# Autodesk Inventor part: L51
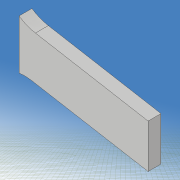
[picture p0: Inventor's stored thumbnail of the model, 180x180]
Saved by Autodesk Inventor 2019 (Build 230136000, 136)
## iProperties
Created: 2021-05
Part Number: L51
Material: 一般
Document SubType Name: Modeling
Designer: kikut
Density: 1 g/cm^3
Appearance: 既定
Mass: 0.00934248 g
Surface Area: 0.426451 cm^2
Volume: 0.00934248 cm^3
Author: kikut
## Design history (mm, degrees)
sketch "スケッチ1"
  geometry: L1 (80, 60)-(-80, 60); L2 (-80, 60)-(-80, -60); L3 (-80, -60)-(80, -60); L4 (80, -60)-(80, 60); L5 (80, 60)-(-80, -60); L6 (-80, 60)-(80, -60); 1 further point
  constraints: 12 end point, 2 midpoint, 2 parallel, 1 horizontal, 1 perpendicular
  dimensions: "d0" = 160 distance of L2.end L3.end; "d1" = 120 distance of L1.end L2.end
extrude "押し出し1" new body sketch "スケッチ1" stored distance "d2" = 0.6; taper "d3" = 0 deg
sketch "スケッチ2"
  geometry: L1 (-140, 0)-(140, 0) reference; L2 (0, -54)-(20, -30); L3 (0, 54)-(20, 30); L4 (0, -3)-(6.514, -3); L5 (6.514, -3)-(16, -6); L6 (16, -6)-(24, -3); L7 (24, -3)-(33.716, -3); L8 (0, 3)-(6.514, 3); L9 (6.514, 3)-(16, 6); L10 (16, 6)-(24, 3); L11 (24, 3)-(33.716, 3); L12 (0, -98)-(0, 98) reference; L13 (-100, -70)-(100, -70); L14 (100, -70)-(100, 70); L15 (100, 70)-(-100, 70); L16 (-100, 70)-(-100, -70); L17 (-100, -70)-(100, 70); L18 (100, -70)-(-100, 70); A1 r 60 centre (54.312, 28.5) between (0, 54) and (0, 3); A2 r 60 centre (54.312, -28.5) between (0, -3) and (0, -54); A3 r 18.111 centre (18, -12) between (20, -30) and (33.716, -3); A4 r 18.111 centre (18, 12) between (33.716, 3) and (20, 30); 1 further point
  constraints: 32 end point, 8 point on circle, 8 symmetric about line, 4 centre point, 3 horizontal, 2 collinear, 2 midpoint, 2 parallel, 1 perpendicular
  dimensions: "d5" = 60 radius of A1; "d6" = 6 distance of L8.start L4.start; "d7" = 108 distance of L3.start L2.start; "d8" = 0 horizontal distance of L3.start L8.start; "d9" = 60 distance of L3.end L2.end; "d10" = 0 horizontal distance of point (0, 0) L3.start; "d11" = 20 horizontal distance of L3.start L3.end; "d12" = 24 distance of A4.centre A3.centre; "d13" = 6 distance of L11.end L7.end; "d14" = 12 distance of L9.end L5.end; "d15" = 16 distance from line of L12 L5.end; "d16" = 24 distance from line of L6.end L12; "d17" = 200 distance of L14.end L15.end; "d18" = 140 distance of L15.end L13.start; "d30" = 18 distance from line of L12 A4.centre
extrude "押し出し2" cut sketch "スケッチ2" stored distance "d19" = 10; taper "d20" = 0 deg
sketch "スケッチ3"
  geometry: L1 (49.705, -17.97)-(33.948, -15.191); L2 (33.948, -15.191)-(34.295, -13.222); L3 (34.295, -13.222)-(50.052, -16); L4 (50.052, -16)-(49.705, -17.97); L5 (49.705, -17.97)-(34.295, -13.222); L6 (33.948, -15.191)-(50.052, -16); L7 (50.052, 16)-(34.295, 13.222); L8 (34.295, 13.222)-(33.948, 15.191); L9 (33.948, 15.191)-(49.705, 17.97); L10 (49.705, 17.97)-(50.052, 16); L11 (50.052, 16)-(33.948, 15.191); L12 (34.295, 13.222)-(49.705, 17.97); L13 (-112, 0)-(112, 0) reference; L14 (0, -84)-(0, 84) reference; 3 further points
  constraints: 24 end point, 4 midpoint, 4 parallel, 2 perpendicular, 2 symmetric about line
  dimensions: "d21" = 2 distance of L3.end L1.start; "d22" = 2 distance of L9.end L7.start; "d23" = 16 distance of L8.end L9.end; "d24" = 42 distance from line of L14 point (42, 15.596); "d26" = 10 deg angle of L7 L13; "d62" = 16 distance from line of L3.end L13
extrude "押し出し3" join sketch "スケッチ3" distance "d27" = 0.6; taper "d28" = 0 deg
fillet "フィレット1" dims "d31" = 2
fillet "フィレット2" dims "d32" = 1
sketch "スケッチ7"
  geometry: L1 (-20, 60)-(80, 60); L2 (80, 60)-(80, -60); L3 (80, -60)-(-20, -60); L4 (-20, -60)-(-20, 60); L5 (0, -82.207)-(0, 85.793) reference; L6 (-40, 0)-(100, 0) reference; L7 (37, -10)-(43, -10); L8 (43, -10)-(43, -20); L9 (43, -20)-(37, -20); L10 (37, -20)-(37, -10); 1 further point
  constraints: 16 end point, 4 parallel, 2 horizontal, 2 perpendicular, 1 other
  dimensions: "d80" = 120 distance of L3.end L1.start; "d81" = 20 distance between parallel lines of L5 L4; "d82" = 100 distance of L1.start L1.end; "d84" = 6 distance of L8.end L9.end; "d85" = 10 distance of L7.end L8.end; "d86" = 57 distance between parallel lines of L4 L10; "d93" = 40 distance between parallel lines of L3 L9
extrude "押し出し5" cut sketch "スケッチ7" stored distance "d87" = 10; taper "d88" = 0 deg
node "ソリッド1"
